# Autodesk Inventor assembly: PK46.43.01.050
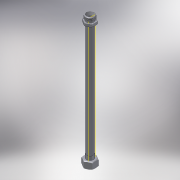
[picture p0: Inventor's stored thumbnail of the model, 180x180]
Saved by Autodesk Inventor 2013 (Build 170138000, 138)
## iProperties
Shininess: 64.0
Length Units: 11269
Angle Units: 11279
Time Units: 11290
Mass Units: 11283
Length Display Precision: 3
Angle Display Precision: 2
Compacted: True
Created: 2004-12
Part Number: PK46.43.01.050
Document SubType Name: Assembly
Designer: ELarisa
Manufacturer: Standard
Standards Organization: Custom
Density: 0.0
Volumn: 0.0
Area: 0.0
PropertySet Name: Model Information
Control State: 0
Master: False
Checked Out: False
Checked Out Date: 2008-10-09
Last Check In Date: 2008-10-09
Author: ELarisa
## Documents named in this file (5)
- C:\Product Design Suite 2013 Test Drive\Dynamic Simulation\Workspace\Assy, Chassis, Front\PK46.43.01.050.iam
- C:\Product Design Suite 2013 Test Drive\Dynamic Simulation\Workspace\Assy, Chassis, Front\PK46.43.01.017.ipt
- C:\Product Design Suite 2013 Test Drive\Dynamic Simulation\Workspace\Assy, Chassis, Front\027.03.04.034.ipt
- C:\Product Design Suite 2013 Test Drive\Dynamic Simulation\Workspace\Assy, Chassis, Front\027.08.00.004.ipt
- C:\Product Design Suite 2013 Test Drive\Dynamic Simulation\Workspace\Assy, Chassis, Front\027.07.03.005.ipt
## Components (4 placed, 4 different names)
1. PK46.43.01.017:1 — Insert:4
2. 027.08.00.004:1 — Вставка:3
3. 027.07.03.005:1 — Вставка:3
4. 027.03.04.034:1 — Insert:4
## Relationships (2: Insert 2)
- Вставка:3 [Insert]: 027.08.00.004:1 ↔ 027.07.03.005:1
- Insert:4: PK46.43.01.017:1 ↔ 027.03.04.034:1
